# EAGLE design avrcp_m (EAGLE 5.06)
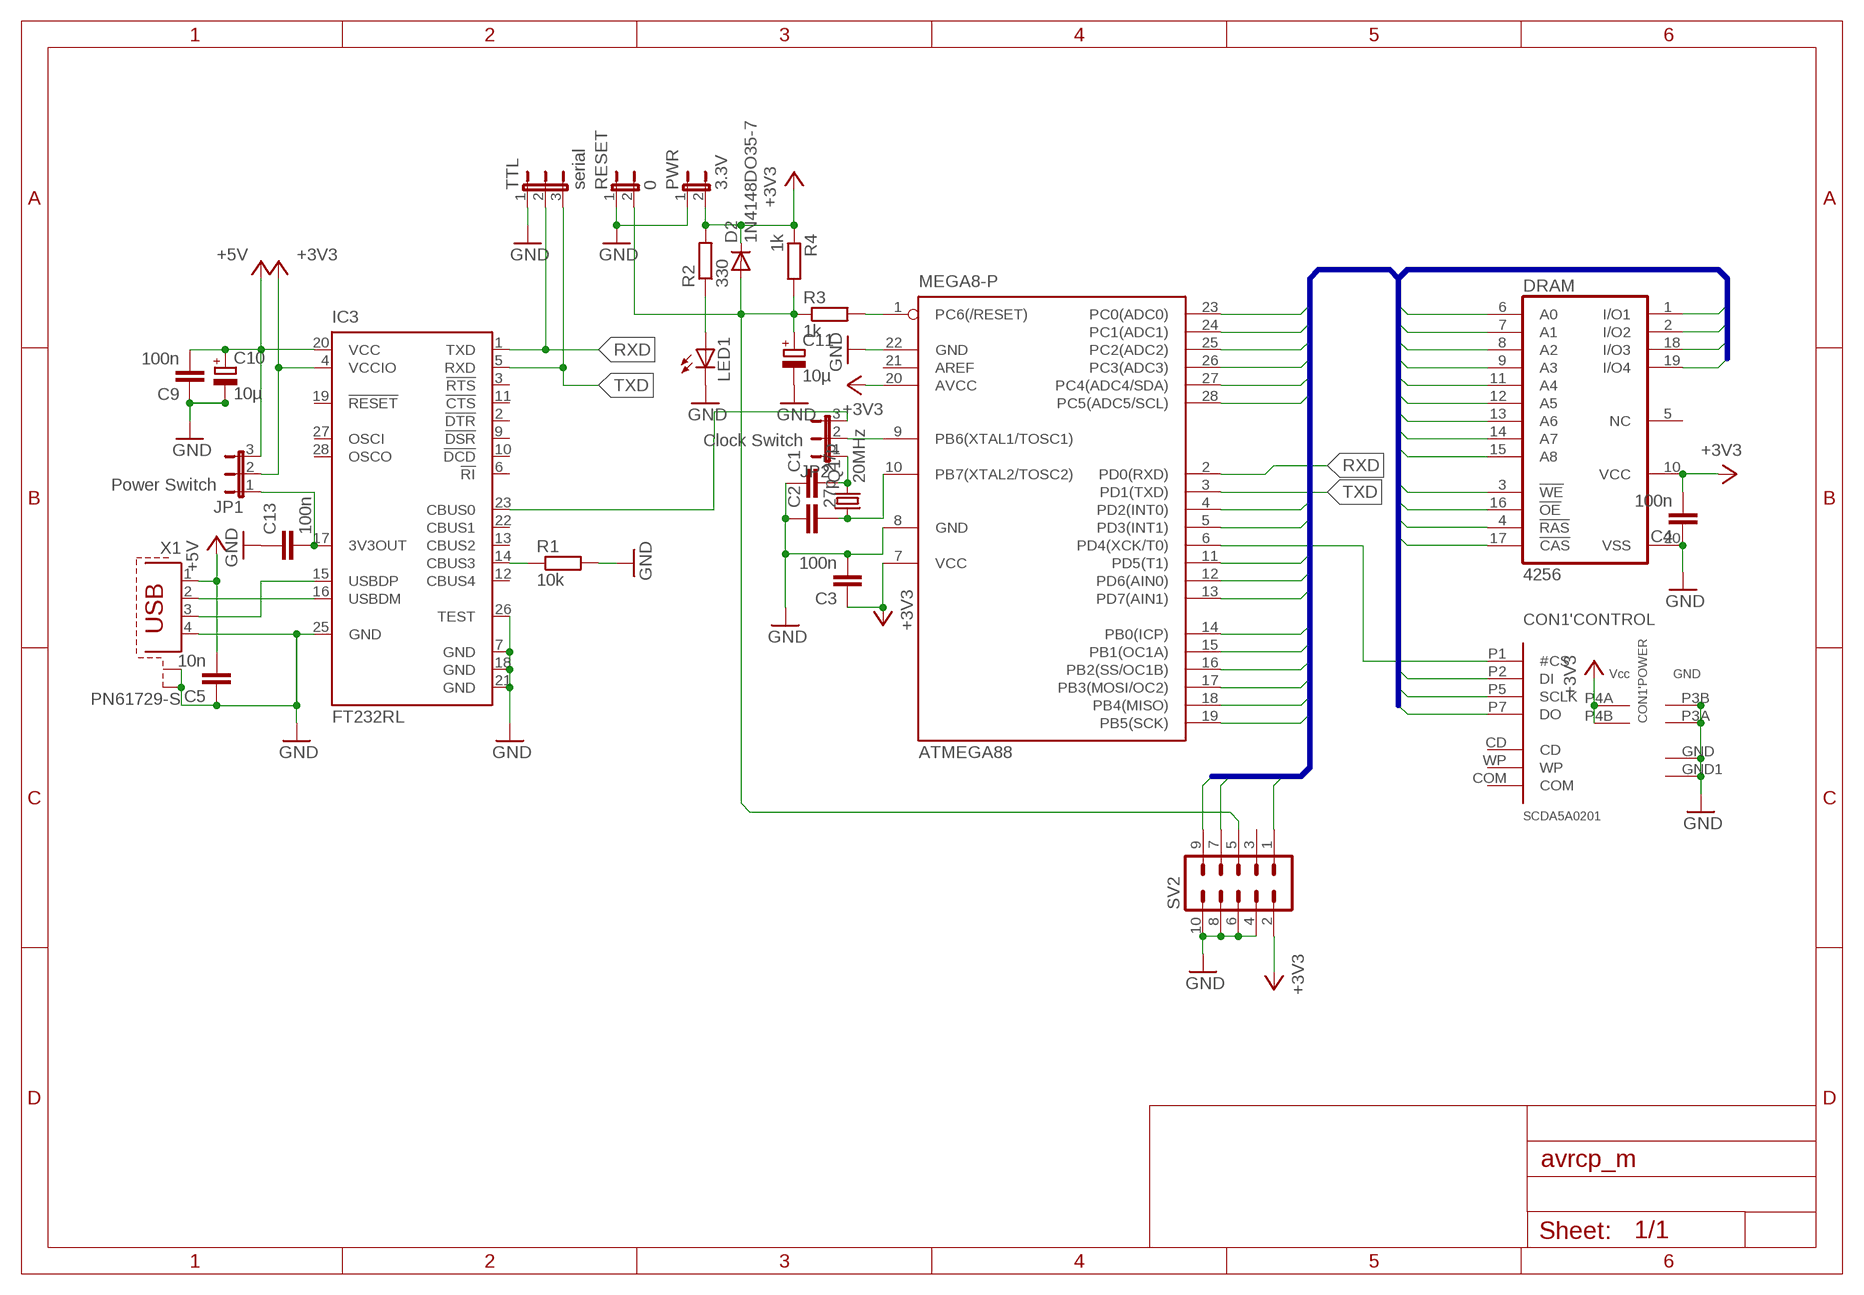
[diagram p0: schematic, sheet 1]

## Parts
ATMEGA88  MEGA8-P  [DIL28-3]
C1  27p  C-EU025-024X044  [C025-024X044]
C2  27p  C-EU025-024X044  [C025-024X044]
C3  100n  C-EU025-024X044  [C025-024X044]
C4  100n  C-EU025-024X044  [C025-024X044]
C5  10n  C-EU025-024X044  [C025-024X044]
C9  100n  C-EU025-024X044  [C025-024X044]
C10  10µ  CPOL-EUE2-5  [E2-5]
C11  10µ  CPOL-EUE2.5-5  [E2,5-5]
C13  100n  C-EU025-024X044  [C025-024X044]
CON1  SCDA5A0201  [SCDA5A0201]
D2  1N4148DO35-7  [DO35-7]
DRAM  4256  514256ALP  [DIL20]
IC3  FT232RL  [SSOP28]
JP1  Power Switch  JP2E  [JP2]
JP2  Clock Switch  JP2E  [JP2]
LED1  LED3MM  [LED3MM]
PWR  3.3V  JP1E  [JP1]
Q1  20MHz  CRYSTALHC49U-V  [HC49U-V]
R1  10k  R-EU_0207/7  [0207/7]
R2  330  R-EU_0207/7  [0207/7]
R3  1k  R-EU_0207/7  [0207/7]
R4  1k  R-EU_0207/7  [0207/7]
RESET  0  JP1E  [JP1]
SV2  ML10  [ML10]
TTL  serial  JP2E  [JP2]
X1  PN61729-S  [PN61729-S]

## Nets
+3V3: ATMEGA88.7(VCC) ATMEGA88.20(AVCC) C3.1 C4.2 CON1.P4A('POWER:VCC) CON1.P4B('POWER:VCC1) D2.C DRAM.10(VCC) IC3.4(VCCIO) JP1.2 PWR.2 R2.2 R4.1 SV2.2
+5V: C5.2 C9.2 C10.+ IC3.20(VCC) JP1.3 X1.1
A0: ATMEGA88.18(PB4(MISO)) CON1.P7('CONTROL:DO) DRAM.6(A0) SV2.9
A1: ATMEGA88.17(PB3(MOSI/OC2)) CON1.P2('CONTROL:DI) DRAM.7(A1) SV2.1
A2: ATMEGA88.16(PB2(SS/OC1B)) DRAM.8(A2)
A3: ATMEGA88.15(PB1(OC1A)) DRAM.9(A3)
A4: ATMEGA88.14(PB0(ICP)) DRAM.11(A4)
A5: ATMEGA88.11(PD5(T1)) DRAM.12(A5)
A6: ATMEGA88.12(PD6(AIN0)) DRAM.13(A6)
A7: ATMEGA88.13(PD7(AIN1)) DRAM.14(A7)
A8: ATMEGA88.5(PD3(INT1)) DRAM.15(A8)
CAS: ATMEGA88.28(PC5(ADC5/SCL)) DRAM.17(!CAS)
GND: ATMEGA88.8(GND) ATMEGA88.22(GND) C1.1 C2.1 C3.2 C4.1 C5.1 C9.1 C10.- C11.- C13.1 CON1.GND1('POWER:GND) CON1.GND('POWER:GND) CON1.P3A('POWER:GND) CON1.P3B('POWER:GND) DRAM.20(VSS) IC3.7(GND) IC3.18(GND) IC3.21(GND) IC3.25(GND) IC3.26(TEST) LED1.K(C) PWR.1 R1.2 RESET.1 SV2.4 SV2.6 SV2.8 SV2.10 TTL.1 X1.4 X1.S1 X1.S2
IO1: ATMEGA88.23(PC0(ADC0)) DRAM.1(I/O1)
IO2: ATMEGA88.25(PC2(ADC2)) DRAM.2(I/O2)
IO3: ATMEGA88.27(PC4(ADC4/SDA)) DRAM.18(I/O3)
IO4: ATMEGA88.26(PC3(ADC3)) DRAM.19(I/O4)
N$1: IC3.14(CBUS3) R1.1
N$2: C13.2 IC3.17(3V3OUT) JP1.1
N$3: ATMEGA88.6(PD4(XCK/T0)) CON1.P1('CONTROL:#CS)
N$4: ATMEGA88.9(PB6(XTAL1/TOSC1)) JP2.2
N$5: ATMEGA88.10(PB7(XTAL2/TOSC2)) C2.2 Q1.1
N$6: C1.2 JP2.1 Q1.2
N$7: LED1.A R2.1
N$8: IC3.23(CBUS0) JP2.3
N$9: IC3.16(USBDM) X1.2
N$10: IC3.15(USBDP) X1.3
N$11: C11.+ D2.A R3.1 R4.2 RESET.2 SV2.5
N$12: ATMEGA88.1(PC6(/RESET)) R3.2
OE: ATMEGA88.4(PD2(INT0)) DRAM.16(!OE)
RAS: ATMEGA88.19(PB5(SCK)) CON1.P5('CONTROL:SCLK) DRAM.4(!RAS) SV2.7
RXD: ATMEGA88.2(PD0(RXD)) IC3.1(TXD) TTL.2
TXD: ATMEGA88.3(PD1(TXD)) IC3.5(RXD) TTL.3
WE: ATMEGA88.24(PC1(ADC1)) DRAM.3(!WE)
Unconnected: ATMEGA88.21(AREF) CON1.CD('CONTROL:CD) CON1.COM('CONTROL:COM) CON1.WP('CONTROL:WP) DRAM.5(NC) IC3.2(!DTR) IC3.3(!RTS) IC3.6(!RI) IC3.9(!DSR) IC3.10(!DCD) IC3.11(!CTS) IC3.12(CBUS4) IC3.13(CBUS2) IC3.19(!RESET) IC3.22(CBUS1) IC3.27(OSCI) IC3.28(OSCO) SV2.3

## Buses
A[0..8],WE,OE,RAS,CAS,IO[1..4]

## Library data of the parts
ATMEGA88 = atmel:MEGA8-P: MICROCONTROLLER 8 Kbytes FLASH, 1 kbytes SRAM, 512 bytes EEPROM, USART, 4-channel 10 bit ADC, 2-channel 8 bit ADC Pin compatible with Atmega48, ATMega88, ATMega168 Source: avr.lbr
C1-C5 C9 C13 = rcl:C-EU: CAPACITOR, European symbol
C10 C11 = rcl:CPOL-EU: POLARIZED CAPACITOR, European symbol
CON1 = SCDA5A0201:SCDA5A0201: ALPS Connector for SDMemory Card SD-CARD SCDA5A0201 SPI -MODE
D2 = diode:1N4148: DIODE
DRAM = memory-hitachi:514256ALP: MEMORY
IC3 = ftdichip:FT232R: Source: http://www.ftdichip.com/Documents/DataSheets/DS_FT232R_v104.pdf
JP1 JP2 TTL = jumper:JP2E: JUMPER
LED1 = led:LED: LED
PWR RESET = jumper:JP1E: JUMPER
Q1 = crystal:CRYSTAL: CRYSTAL
R1-R4 = rcl:R-EU_: RESISTOR, European symbol
SV2 = con-harting-ml:ML10: HARTING
X1 = con-berg:PN61729-S: BERG USB connector

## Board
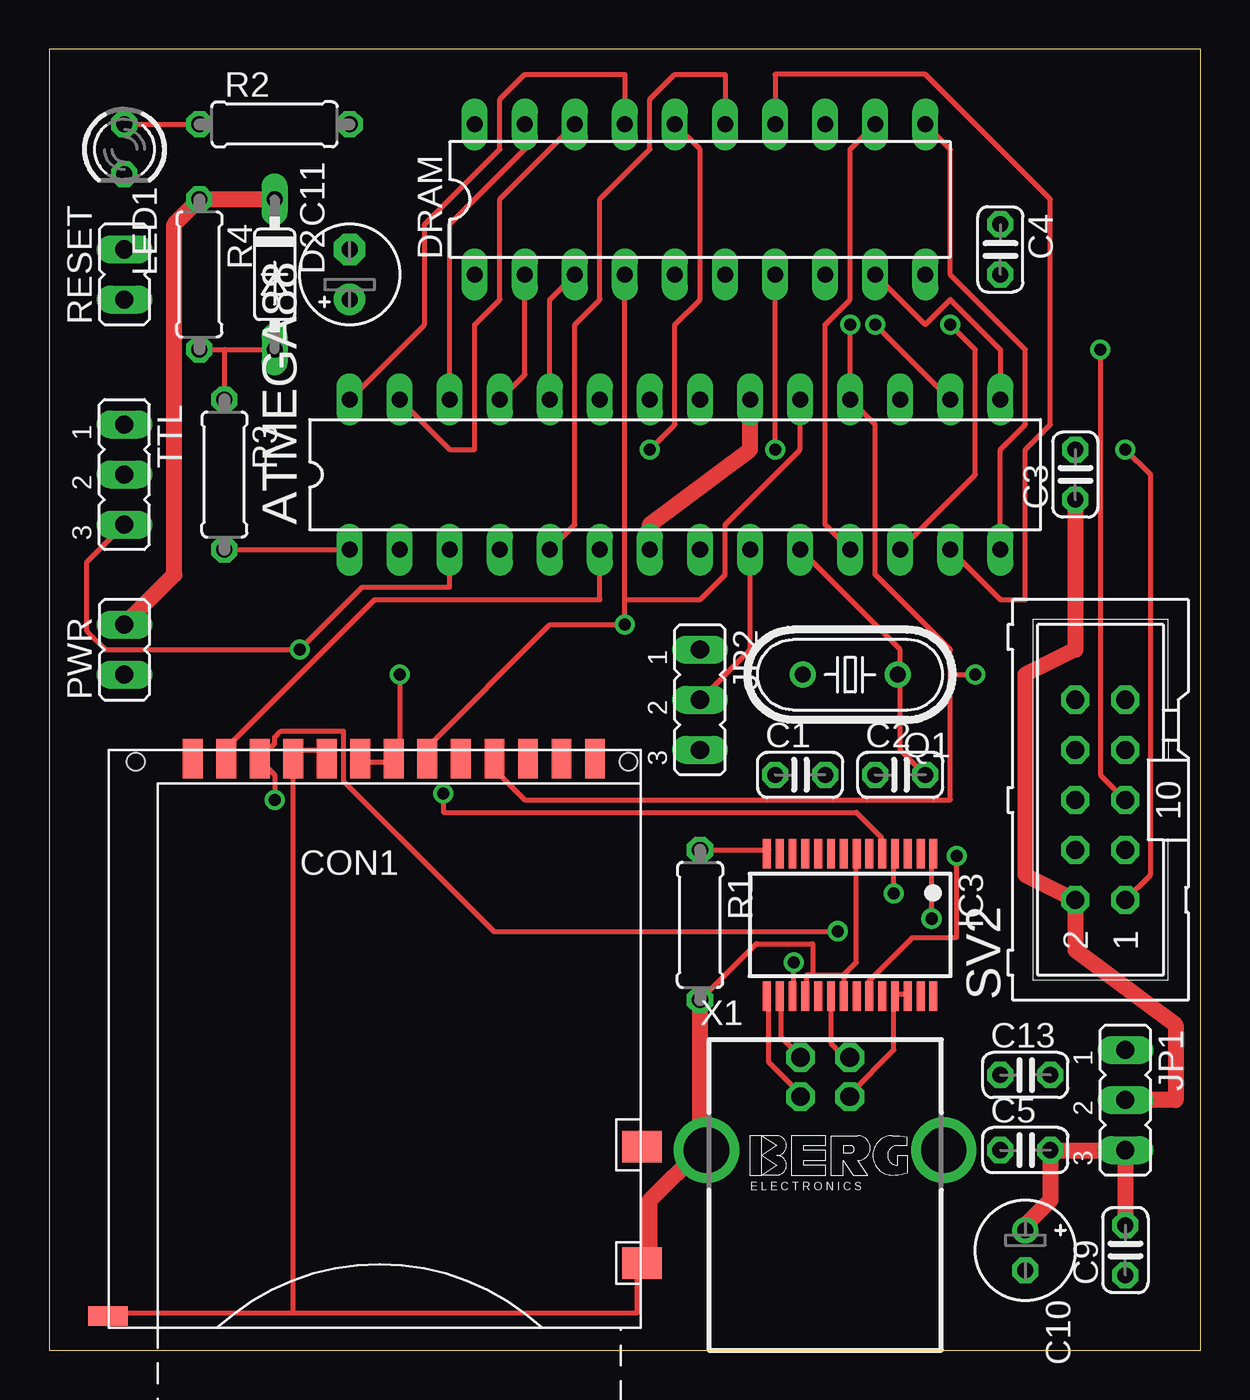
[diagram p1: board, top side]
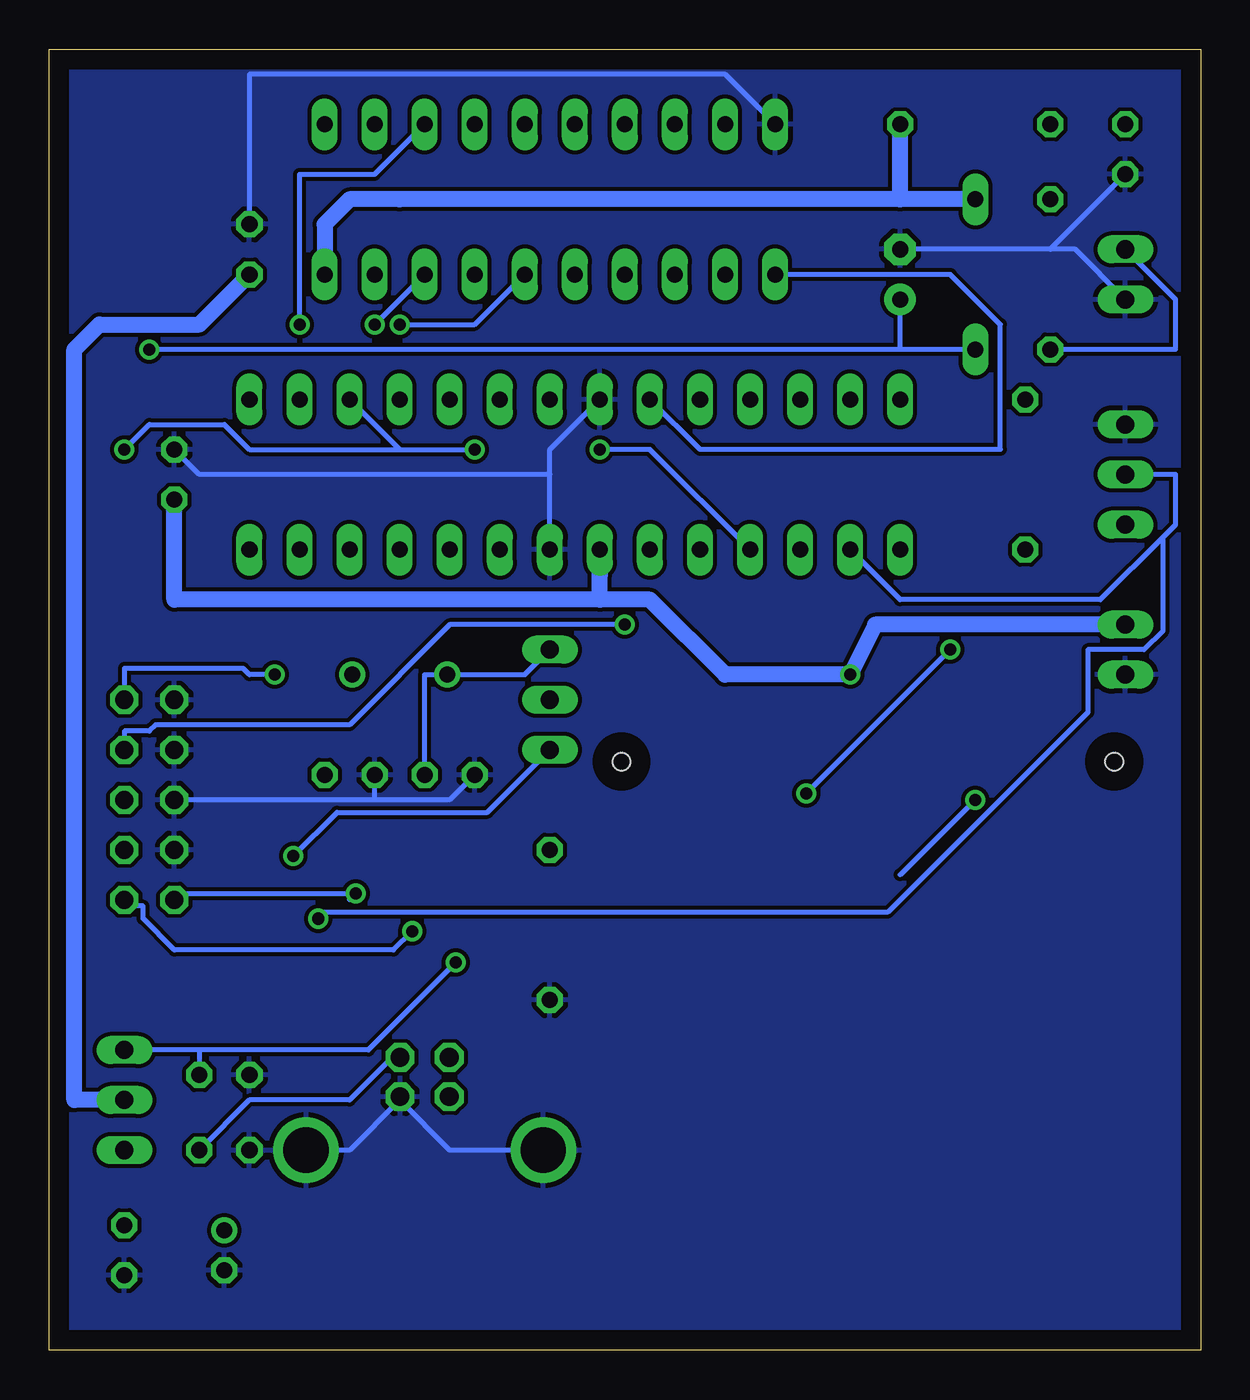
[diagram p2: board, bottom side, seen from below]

Size 58.42 x 66.04 mm. Coordinates in mm from the lower left corner, seen from the top.
Outline: 58.42,66.04 0,66.03 0,0 58.42,0 58.42,66.04
Copper layers (1*16): Top 0.035mm / dielectric 1.5mm / Bottom 0.035mm
Design rules "default": minimum track width 10mil, minimum drill 24mil, track to track 8mil, track to pad 8mil, pad to pad 8mil, via to via 8mil, smd to smd 8mil, copper to edge 40mil, drill to drill 8mil, minimum pad ring 10mil, minimum via ring 8mil, stop-mask expansion 4mil, vias tented up to drill 0mil, thermal gap 10mil

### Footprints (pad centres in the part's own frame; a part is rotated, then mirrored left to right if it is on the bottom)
DIL28-3 = drill 0.813 long: 1 -16.51,-3.81; 2 -13.97,-3.81; 3 -11.43,-3.81; 4 -8.89,-3.81; 5 -6.35,-3.81; 6 -3.81,-3.81; 7 -1.27,-3.81; 8 1.27,-3.81; 9 3.81,-3.81; 10 6.35,-3.81; 11 8.89,-3.81; 12 11.43,-3.81; 13 13.97,-3.81; 14 16.51,-3.81; 15 16.51,3.81; 16 13.97,3.81; 17 11.43,3.81; 18 8.89,3.81; 19 6.35,3.81; 20 3.81,3.81; 21 1.27,3.81; 22 -1.27,3.81; 23 -3.81,3.81; 24 -6.35,3.81; 25 -8.89,3.81; 26 -11.43,3.81; 27 -13.97,3.81; 28 -16.51,3.81
C025-024X044 = drill 0.813 octagon: 1 -1.27,0; 2 1.27,0
E2-5 = drill 0.813 pad 1.27 round: + -1.016,0 | drill 0.813 pad 1.27 octagon: - 1.016,0
E2,5-5 = drill 0.813 pad 1.6 round: + -1.27,0 | drill 0.813 pad 1.6 octagon: - 1.27,0
SCDA5A0201 = smd 1 x 2: CD 9.475,-0.45; COM 11.175,-0.45; P1 -7.525,-0.45; P2 -5.825,-0.45; P3A -4.125,-0.45; P3B -2.425,-0.45; P4A -0.725,-0.45; P4B 0.975,-0.45; P5 2.675,-0.45; P6 4.375,-0.45; P7 6.075,-0.45; P8 7.775,-0.45; P9 -9.225,-0.45 | smd 2 x 1.6: GND 13.575,-26.05; WP 13.575,-20.15 | smd 2 x 1: GND1 -13.525,-28.75 | hole 0.9: -12.125,-0.6; 12.875,-0.6
DO35-7 = drill 0.813 long: A 3.81,0; C -3.81,0
DIL20 = drill 0.813 long: 1 -11.43,-3.81; 2 -8.89,-3.81; 3 -6.35,-3.81; 4 -3.81,-3.81; 5 -1.27,-3.81; 6 1.27,-3.81; 7 3.81,-3.81; 8 6.35,-3.81; 9 8.89,-3.81; 10 11.43,-3.81; 11 11.43,3.81; 12 8.89,3.81; 13 6.35,3.81; 14 3.81,3.81; 15 1.27,3.81; 16 -1.27,3.81; 17 -3.81,3.81; 18 -6.35,3.81; 19 -8.89,3.81; 20 -11.43,3.81
SSOP28 = smd 0.4 x 1.5: 1 -4.225,-3.625; 2 -3.575,-3.625; 3 -2.925,-3.625; 4 -2.275,-3.625; 5 -1.625,-3.625; 6 -0.975,-3.625; 7 -0.325,-3.625; 8 0.325,-3.625; 9 0.975,-3.625; 10 1.625,-3.625; 11 2.275,-3.625; 12 2.925,-3.625; 13 3.575,-3.625; 14 4.225,-3.625; 15 4.225,3.625; 16 3.575,3.625; 17 2.925,3.625; 18 2.275,3.625; 19 1.625,3.625; 20 0.975,3.625; 21 0.325,3.625; 22 -0.325,3.625; 23 -0.975,3.625; 24 -1.625,3.625; 25 -2.275,3.625; 26 -2.925,3.625; 27 -3.575,3.625; 28 -4.225,3.625
JP2 = drill 0.914 long: 1 -2.54,0; 2 0,0; 3 2.54,0
LED3MM = drill 0.813 octagon: A -1.27,0; K 1.27,0
JP1 = drill 0.914 long: 1 0,-1.27; 2 0,1.27
HC49U-V = drill 0.813 round: 1 -2.413,0; 2 2.413,0
0207/7 = drill 0.813 octagon: 1 -3.81,0; 2 3.81,0
ML10 = drill 0.914 octagon: 1 -5.08,-1.27; 2 -5.08,1.27; 3 -2.54,-1.27; 4 -2.54,1.27; 5 0,-1.27; 6 0,1.27; 7 2.54,-1.27; 8 2.54,1.27; 9 5.08,-1.27; 10 5.08,1.27
PN61729-S = drill 0.95 octagon: 1 1.25,4.71; 2 -1.25,4.71; 3 -1.25,2.71; 4 1.25,2.71 | drill 2.3 pad 2.9 round: S1 -6.02,0; S2 6.02,0

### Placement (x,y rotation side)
ATMEGA88  31.75,44.45 0 top
C1  38.1,29.21 0 top
C2  43.18,29.21 0 top
C3  52.07,44.45 90 top
C4  48.26,55.88 270 top
C5  49.53,10.16 0 top
C9  54.61,5.08 90 top
C10  49.53,5.08 270 top
C11  15.24,54.61 90 top
C13  49.53,13.97 0 top
CON1  16.51,30.48 0 top
D2  11.43,54.61 270 top
DRAM  33.02,58.42 0 top
IC3  40.64,21.59 180 top
JP1  54.61,12.7 270 top
JP2  33.02,33.02 270 top
LED1  3.81,60.96 270 top
PWR  3.81,35.56 0 top
Q1  40.64,34.29 180 top
R1  33.02,21.59 270 top
R2  11.43,62.23 0 top
R3  8.89,44.45 270 top
R4  7.62,54.61 270 top
RESET  3.81,54.61 0 top
SV2  53.34,27.94 90 top
TTL  3.81,44.45 270 top
X1  39.37,10.16 0 top

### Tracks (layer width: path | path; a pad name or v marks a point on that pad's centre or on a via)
+3V3  (via drill 0.61)
  Top 0.254: v17.78,34.29 17.78,30.48 CON1.P4B 17.14,29.84 15.88,29.84 CON1.P4A | v42.86,23.18 42.86,25.08 IC3.4
  Top 0.813: D2.C R4.1 6.35,57.15 6.35,39.37 PWR.2 | C3.1 52.07,35.56 49.53,34.29 49.53,24.13 SV2.2 52.07,20.32 57.15,16.51 57.15,12.7 JP1.2 | ATMEGA88.7 30.48,41.91 35.56,45.72 ATMEGA88.20
  Bottom 0.254: 43.18,22.86 v42.86,23.18 51.75,23.18 SV2.2
  Bottom 0.813: DRAM.10 44.45,57.15 43.18,58.42 40.64,58.42 15.24,58.42 | D2.C 15.24,58.42 | 15.24,58.42 R2.2 | PWR.2 16.51,36.83 v17.78,34.29 24.13,34.29 27.94,38.1 | 27.94,38.1 30.48,38.1 30.48,39.37 ATMEGA88.7 | C3.1 52.07,38.1 27.94,38.1 | C4.2 50.8,52.07 55.88,52.07 57.15,50.8 57.15,12.7 JP1.2
+5V
  Top 0.254: 49.53,6.35 C10.+ | IC3.20 39.69,17.78 39.69,15.56 40.32,14.92 X1.1
  Top 0.813: C9.2 JP1.3 C5.2 50.8,7.62 49.53,6.35
  Bottom 0.254: C5.2 48.26,12.7 43.18,12.7 40.64,15.24 X1.1
A0  (via drill 0.61)
  Top 0.254: 45.72,34.29 45.72,35.56 41.91,39.37 41.91,46.99 ATMEGA88.18 v40.64,52.07 | 45.72,34.29 45.72,27.94 24.13,27.94 22.86,29.21 CON1.P7 | 45.72,34.29 v46.99,34.29
  Bottom 0.254: DRAM.6 36.83,52.07 v40.64,52.07 | SV2.9 54.61,34.61 48.58,34.61 48.26,34.29 v46.99,34.29
A1  (via drill 0.61)
  Top 0.254: v36.83,45.72 DRAM.7 | v11.43,27.94 11.43,29.21 10.79,29.84 CON1.P2 10.79,30.16 11.43,30.8 11.43,31.11 11.75,31.43 14.92,31.43 14.92,28.89 22.54,21.27 v40.01,21.27 | SV2.1 55.88,24.13 55.88,44.45 v54.61,45.72
  Bottom 0.254: 40.64,45.72 v36.83,45.72 | 40.64,45.72 ATMEGA88.17 | v54.61,45.72 53.34,46.99 49.53,46.99 48.26,45.72 40.64,45.72 | v11.43,27.94 15.24,24.13 | v40.01,21.27 40.96,20.32 52.07,20.32 53.66,21.91 53.66,22.54 54.29,22.54 SV2.1
A2  (via drill 0.61)
  Top 0.254: v41.91,52.07 ATMEGA88.16
  Bottom 0.254: DRAM.8 v41.91,52.07
A3
  Top 0.254: DRAM.9 44.45,52.07 45.72,53.34 48.26,50.8 ATMEGA88.15
A4
  Top 0.254: ATMEGA88.14 48.26,45.72 49.53,46.99 49.53,50.8 45.72,54.61 45.72,60.96 DRAM.11
A5
  Top 0.254: ATMEGA88.11 39.37,41.91 39.37,52.07 40.64,53.34 40.64,60.96 DRAM.12
A6  (via drill 0.61)
  Top 0.254: ATMEGA88.12 46.99,44.45 46.99,50.8 v45.72,52.07
  Bottom 0.254: v45.72,52.07 45.72,59.69 41.91,59.69 DRAM.13
A7
  Top 0.254: ATMEGA88.13 48.26,38.1 49.53,38.1 49.53,45.72 50.8,46.99 50.8,58.42 44.45,64.77 36.83,64.77 DRAM.14
A8
  Top 0.254: ATMEGA88.5 26.67,41.91 26.67,52.07 27.94,53.34 27.94,58.42 30.48,60.96 30.48,63.5 31.75,64.77 34.29,64.77 DRAM.15
CAS
  Top 0.254: ATMEGA88.28 19.05,52.07 19.05,57.15 22.86,60.96 22.86,63.5 24.13,64.77 29.21,64.77 DRAM.17
GND
  Top 0.254: CON1.P3B 13.97,30.48 12.7,30.48 CON1.P3A 12.38,29.84 12.38,1.91 | 30.48,5.08 CON1.GND 29.84,4.13 29.84,1.91 12.38,1.91 | IC3.26 43.5,18.1 42.86,18.1 IC3.25 42.86,17.78 42.86,15.24 40.64,13.02 X1.4 | 38.73,19.05 40.32,19.05 | 38.73,19.05 38.42,19.05 38.42,18.1 IC3.18 | 40.32,19.05 40.32,18.1 IC3.21 | 40.32,19.05 40.96,19.68 40.96,25.08 IC3.7 | R1.2 35.88,20.64 38.73,20.64 38.73,19.05 | 12.38,1.91 3.17,1.91 CON1.GND1 | C10.- 49.53,3.81 C10.- | 33.02,10.16 X1.S1 33.02,10.16
  Top 0.813: R1.2 33.02,10.16 30.48,7.62 30.48,5.08
  Bottom 0.254: 7.62,55.88 LED1.K | 7.62,55.88 C11.- | RESET.1 6.35,55.88 7.62,55.88 | C1.1 38.1,27.94 41.91,27.94 | 41.91,27.94 SV2.6 | 41.91,27.94 C2.1 | 33.02,44.45 33.02,45.72 ATMEGA88.22 | ATMEGA88.8 33.02,44.45 | 33.02,44.45 50.8,44.45 C3.2 | 40.64,12.7 43.18,10.16 44.45,10.16 X1.S2 | 40.64,12.7 X1.4 40.64,12.7 | 40.64,12.7 38.1,10.16 34.29,10.16 X1.S1 | C4.1 48.26,64.77 24.13,64.77 DRAM.20
  pour Bottom: 0,66.04 58.42,66.04 58.42,0 0,0
IO1
  Bottom 0.254: DRAM.1 12.7,54.61 10.16,52.07 10.16,45.72 25.4,45.72 ATMEGA88.23
IO2
  Top 0.254: ATMEGA88.25 24.13,49.53 DRAM.2
IO3
  Top 0.254: ATMEGA88.27 20.32,45.72 21.59,45.72 21.59,52.07 22.86,53.34 22.86,58.42 DRAM.18
IO4
  Top 0.254: ATMEGA88.26 20.32,57.15 24.13,60.96 DRAM.19
N$1
  Top 0.254: R1.1 36.51,25.4 IC3.14
N$2  (via drill 0.61)
  Top 0.254: v37.78,19.68 37.78,18.1 IC3.17
  Bottom 0.254: 50.8,15.24 C13.2 | 50.8,15.24 JP1.1 | v37.78,19.68 42.23,15.24 50.8,15.24
N$3
  Top 0.254: ATMEGA88.6 27.94,38.1 16.51,38.1 8.89,30.48 CON1.P1
N$4
  Top 0.254: ATMEGA88.9 35.56,35.56 JP2.2
N$5
  Top 0.254: C2.2 43.18,30.48 43.18,34.29 | 43.18,34.29 Q1.1 43.18,34.29 | ATMEGA88.10 43.18,35.56 43.18,34.29
N$6
  Bottom 0.254: C1.2 39.37,34.29 Q1.2 | Q1.2 38.1,34.29 | Q1.2 38.1,34.29 | JP2.1 34.29,34.29 38.1,34.29 | Q1.2 38.1,34.29
N$7
  Top 0.254: LED1.A R2.1
N$8  (via drill 0.61)
  Top 0.254: v46.04,25.08 46.04,20.95 43.81,20.95 41.59,18.73 41.59,18.1 IC3.23
  Bottom 0.254: v46.04,25.08 43.81,27.3 36.2,27.3 JP2.3
N$9
  Top 0.254: IC3.16 37.15,17.78 37.15,15.88 38.1,14.92 X1.2
N$10
  Top 0.254: IC3.15 36.51,17.78 36.51,14.61 38.1,13.02 X1.3
N$11  (via drill 0.61)
  Top 0.254: 8.89,50.8 R3.1 8.89,50.8 | R4.2 8.89,50.8 | 8.89,50.8 D2.A | SV2.5 53.34,29.21 v53.34,50.8
  Bottom 0.254: RESET.2 1.27,53.34 1.27,50.8 R4.2 | D2.A 15.24,50.8 | 15.24,50.8 v53.34,50.8 | 15.24,50.8 C11.+
N$12
  Top 0.254: R3.2 ATMEGA88.1
OE  (via drill 0.61)
  Top 0.254: v30.48,45.72 31.75,46.99 31.75,52.07 33.02,53.34 33.02,60.96 DRAM.16
  Bottom 0.254: ATMEGA88.4 27.94,45.72 v30.48,45.72
RAS  (via drill 0.61)
  Top 0.254: 29.21,38.1 DRAM.4 | 29.21,38.1 v29.21,36.83 25.4,36.83 19.05,30.48 CON1.P5 | ATMEGA88.19 38.1,45.72 34.29,41.91 34.29,39.37 33.02,38.1 29.21,38.1
  Bottom 0.254: v29.21,36.83 38.1,36.83 43.18,31.75 53.02,31.75 53.34,31.43 54.61,31.43 SV2.7
RXD  (via drill 0.61)
  Top 0.254: v44.77,21.91 44.77,25.08 IC3.1
  Bottom 0.254: ATMEGA88.2 15.24,38.1 5.08,38.1 1.91,41.27 | 1.91,41.27 1.27,41.91 1.27,44.45 TTL.2 | v44.77,21.91 44.45,22.23 15.88,22.23 5.71,32.38 5.71,35.56 2.86,35.56 1.91,36.51 1.91,41.27
TXD  (via drill 0.61)
  Top 0.254: IC3.5 42.23,25.4 42.23,26.04 40.96,27.3 20,27.3 v20,28.26 | ATMEGA88.3 20.32,38.73 15.88,38.73 v12.7,35.56 2.86,35.56 1.91,36.51 1.91,40.01 TTL.3
  Bottom 0.254: v12.7,35.56 v20,28.26
WE
  Top 0.254: ATMEGA88.24 25.4,53.34 DRAM.3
